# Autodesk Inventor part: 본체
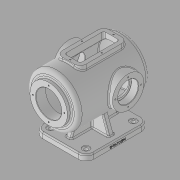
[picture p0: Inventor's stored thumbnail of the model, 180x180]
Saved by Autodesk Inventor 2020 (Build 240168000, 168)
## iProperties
Created: 2021-11
Part Number: 본체
Material: 일반
Document SubType Name: Modeling
Designer: Administrator
Density: 1 g/cm^3
Appearance: 기본값
Mass: 1311.31 g
Surface Area: 2404.16 cm^2
Volume: 1311.31 cm^3
Author: Administrator
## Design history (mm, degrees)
sketch "스케치1"
  geometry: L1 (-80, -65)-(80, -65); L2 (80, -65)-(80, 65); L3 (80, 65)-(-80, 65); L4 (-80, 65)-(-80, -65); L5 (-80, -65)-(80, 65); L6 (80, -65)-(-80, 65); 1 further point
  constraints: 12 end point, 2 midpoint, 2 parallel, 1 horizontal, 1 perpendicular
  dimensions: "d0" = 160 distance of L2.end L3.end; "d1" = 130 distance of L1.end L2.end
extrude "돌출1" new body sketch "스케치1" distance "d2" = 14; taper "d3" = 0 deg
sketch "스케치2"
  geometry: L1 (-100, 114)-(110, 114); L2 (110, 114)-(110, 161.5); L3 (80, 0)-(80, 14) reference; L4 (110, 161.5)-(100, 161.5); L5 (100, 161.5)-(100, 179); L6 (100, 179)-(-75.993, 179); L7 (80, 0)-(-80, 0) reference; L8 (110, 146.5)-(85, 146.5); L9 (85, 146.5)-(85, 169); L10 (85, 169)-(-71.239, 169); A1 r 100 centre (0, 114) between (-75.993, 179) and (-100, 114); A2 r 90 centre (0, 114) between (-71.239, 169) and (-90, 114); 1 further point
  constraints: 16 end point, 4 perpendicular, 4 point on circle, 3 point on line, 2 centre point, 2 horizontal
  dimensions: "d4" = 30 distance between parallel lines of L2 L3; "d5" = 100 radius of A1; "d6" = 95 diameter of L4 L1; "d7" = 130 diameter of L6 L1; "d8" = 114 distance from line of L1.start L7; "d9" = 210 distance from line of L1.start L2; "d10" = 10 distance of L2.end L4.end; "d11" = 10 radial gap between concentric circles of A1 A2; "d12" = 25 distance of L8.start L8.end; "d13" = 65 diameter of L8 L1; "d14" = 110 diameter of L10 L1
revolve "회전1" sketch "스케치2" stored, may be unused: angle "d15" = 90 deg
node "작업 평면1"
sketch "스케치3"
  geometry: L1 (-60, -30)-(60, -30); L2 (60, -30)-(60, 30); L3 (60, 30)-(-60, 30); L4 (-60, 30)-(-60, -30); L5 (-60, -30)-(60, 30); L6 (60, -30)-(-60, 30); L7 (-110, 47.5)-(-110, -47.5) reference; L8 (-50, 20)-(50, 20); L9 (50, 20)-(50, -20); L10 (50, -20)-(-50, -20); L11 (-50, -20)-(-50, 20); 4 further points
  constraints: 20 end point, 4 midpoint, 4 parallel, 2 perpendicular, 1 horizontal, 1 horizontal alignment, 3 other
  dimensions: "d17" = 50 distance between parallel lines of L7 L4; "d18" = 120 distance between parallel lines of L2 L4; "d19" = 60 distance between parallel lines of L1 L3; "d45" = 10 distance between parallel lines of L3 L8
extrude "돌출2" join sketch "스케치3" stored distance "d20" = 14; taper "d21" = 0 deg
node "작업 평면2"
sketch "스케치4"
  geometry: L1 (-110, 161.5)-(-110, 66.5) reference; L2 (-110, 114)-(-65.12, 114); C1 r 40 at (17, 114); 1 further point
  constraints: 2 end point, 1 centre point, 1 horizontal, 1 horizontal alignment, 1 midpoint
  dimensions: "d23" = 127 distance from line of L1 C1.centre; "d24" = 80 diameter of C1
extrude "돌출3" join sketch "스케치4" stored distance "d25" = 14; taper "d26" = 0 deg
sketch "스케치5"
  geometry: C1 r 40 at (0, 0) reference; 2 further points
  constraints: 1 coincident
hole "구멍1" sketch "스케치5" at (0, 0) diameter "d27" = 42; stored, may be unused: countersink angle "d31" = 90 deg, drill point angle "d33" = 118 deg; dims "d28" = 10, "d29" = 52, "d30" = 18, "d32" = 8
sketch "스케치6" dims "d34" = 65
  geometry: L1 (0, 0)-(0, 32.5); C1 r 40 at (0, 0) reference; 2 further points
  constraints: 2 coincident, 2 end point, 1 vertical, 1 vertical alignment, 2 other
hole "구멍2" sketch "스케치6" at (0, 32.5) diameter "d35" = 3.242; stored, may be unused: countersink angle "d39" = 90 deg, drill point angle "d41" = 118 deg; dims "d36" = 11, "d37" = 52, "d38" = 18, "d40" = 13
extrude "돌출4" cut sketch "스케치3" stored distance "d46" = 14; taper "d47" = 0 deg
sketch "스케치7"
  geometry: L1 (-23, 75)-(57, 75) reference; L2 (-23, -75)-(57, -75) reference; L3 (17, 75)-(17, 0); L4 (0, 0)-(24.421, 0); L5 (-110, 47.5)-(-110, -47.5) reference; L6 (-110, 0)-(-29.414, 0); L7 (0, 0)-(0, 30.072); 4 further points
  constraints: 8 end point, 2 horizontal, 2 midpoint, 2 symmetric about line, 2 vertical, 1 point on line, 1 vertical alignment
  dimensions: "d49" = 17 distance from line of point (0, 25) L3; "d50" = 55 horizontal distance of point (-55, 0) point (0, 25); "d52" = 50 distance of point (0, -25) point (0, 25)
hole "구멍3" sketch "스케치7" at (-55, 0), (0, 25), (55, 0), (0, -25) diameter "d53" = 3.242; stored, may be unused: countersink angle "d57" = 90 deg, drill point angle "d59" = 118 deg; dims "d54" = 9, "d55" = 52, "d56" = 18, "d58" = 11
sketch "스케치8"
  geometry: L1 (-65, 14)-(65, 14) reference; L2 (50, 14)-(37.656, 47.916); L3 (-50, 14)-(-38.327, 46.071); L4 (0, 0)-(0, 39.881)
  constraints: 6 end point, 2 point on line, 1 vertical, 1 other
  dimensions: "d60" = 110 deg angle of L1 L2; "d61" = 100 distance of L3.start L2.start
feature "리브1" dims "d62" = 1, "d63" = 14, "d64" = 0, "d65" = 0, "d66" = 1, "d67" = 1
feature "리브2" dims "d68" = 1, "d69" = 14, "d70" = 0, "d71" = 0, "d72" = 1, "d73" = 1
sketch "스케치9"
  geometry: L1 (-80, 14)-(80, 14) reference; L2 (60, 14)-(47.58, 48.123); L3 (-60, 14)-(-45.96, 52.574); L4 (0, 0)-(0, 49.082)
  constraints: 6 end point, 2 point on line, 1 vertical, 1 other
  dimensions: "d74" = 120 distance of L2.start L3.start; "d75" = 110 deg angle of L1 L2
feature "리브3" dims "d76" = 1, "d77" = 14, "d78" = 0, "d79" = 0, "d80" = 1, "d81" = 1
fillet "모깎기1" dims "d82" = 20
sketch "스케치10"
  geometry: A1 r 20 centre (60, -45) between (60, -65) and (80, -45) reference; A2 r 20 centre (60, 45) between (80, 45) and (60, 65) reference; A3 r 20 centre (-60, -45) between (-80, -45) and (-60, -65) reference; A4 r 20 centre (-60, 45) between (-60, 65) and (-80, 45) reference; 5 further points
  constraints: 4 coincident
hole "구멍4" sketch "스케치10" at (60, -45), (60, 45), (-60, -45), (-60, 45) diameter "d83" = 9; stored, may be unused: countersink angle "d87" = 90 deg, drill point angle "d89" = 118 deg; dims "d84" = 9, "d85" = 18, "d86" = 2, "d88" = 11
fillet "모깎기2" dims "d90" = 15
fillet "모깎기3" dims "d91" = 5
sketch "스케치11" dims "d92" = 80
  geometry: L1 (0, 0)-(40, 0); C1 r 47.5 at (0, 0) reference; 2 further points
  constraints: 2 coincident, 2 end point, 1 horizontal, 1 horizontal alignment, 2 other
hole "구멍5" sketch "스케치11" at (40, 0) diameter "d93" = 3.242; stored, may be unused: countersink angle "d97" = 90 deg, drill point angle "d99" = 118 deg; dims "d94" = 11, "d95" = 18, "d96" = 2, "d98" = 13
fillet "모깎기4" dims "d103" = 10
fillet "모깎기5" dims "d104" = 3
fillet "모깎기6" dims "d105" = 3
fillet "모깎기7" dims "d106" = 3
fillet "모깎기8" dims "d107" = 3
chamfer "모따기1" distance "d108" = 1; stored, may be unused: second distance "d109" = 2, angle "d110" = 45 deg
sketch "스케치12"
  geometry: L1 (20.808, 13.931)-(99.192, 13.931); L2 (99.192, 13.931)-(99.192, -3.931); L3 (99.192, -3.931)-(20.808, -3.931); L4 (20.808, -3.931)-(20.808, 13.931); L5 (20.808, 13.931)-(99.192, -3.931); L6 (0, 0)-(120, 0) reference; 3 further points
  constraints: 2 end point, 2 midpoint, 1 vertical alignment, 2 other
  dimensions: "d111" = 5 distance of point (60, 5) point (60, 0)
feature "엠보싱1" sketch "스케치12" dims "d4" = 30, "d5" = 100, "d6" = 95, "d7" = 130, "d8" = 114, "d9" = 210, "d10" = 10, "d11" = 10, "d12" = 25, "d13" = 65, "d14" = 110, "d112" = 0.5, "d113" = 0
fillet "모깎기9" dims "d114" = 3
fillet "모깎기10" dims "d115" = 0.3
node "솔리드1"
pattern_circular "원형 패턴1" dims angle "d43" = 360 deg
mirror "미러1"
mirror "미러2"
pattern_circular "원형 패턴2" dims angle "d101" = 360 deg
feature "A9D066F2-1C7D-4E18-AEED-F7BC21143FA4" dims "d83" = 9, "d84" = 9, "d85" = 18, "d86" = 2, "d87" = 90 deg, "d88" = 11, "d89" = 118 deg
other parameters: "d16" = 184, "d22" = -75
